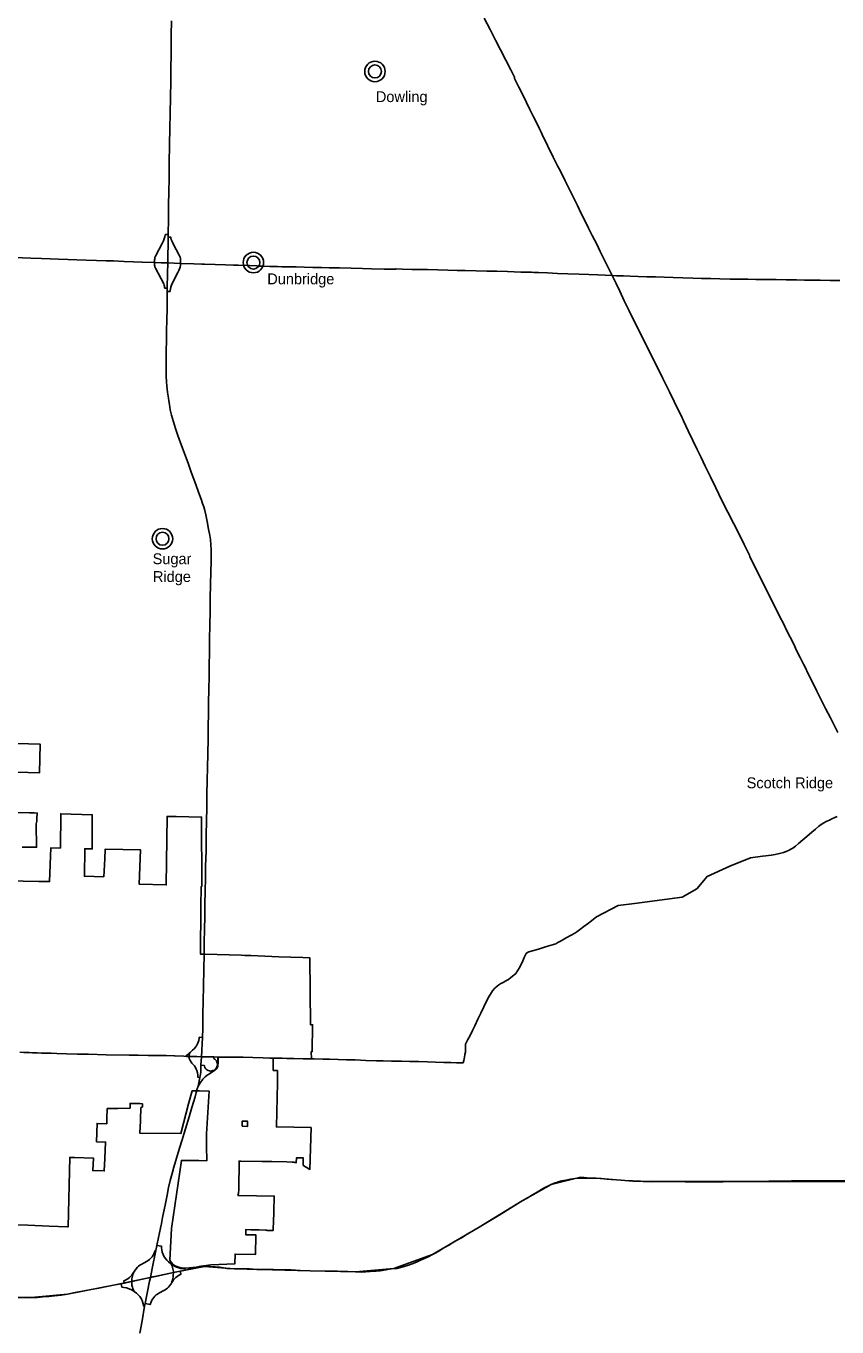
# Model space of a CAD drawing. Extents: x 0 to 851, y 0 to 440.
# Drawn here: x 318.5 to 370.6, y 193.8 to 277.3 of the extents above; entities that cross this region are included whole.
import ezdxf

# ---------------------------------------------------------------- set-up
doc = ezdxf.new("R2010")
doc.units = 0
for name, color, linetype in [('DV_X_Corp_Line', 7, 'Continuous'), ('GM_X_Interchange_Ramps', 7, 'Continuous'), ('GM_X_Interstate_Route', 7, 'Continuous'), ('GM_X_State_Route', 7, 'Continuous'), ('GM_X_US_Route', 7, 'Continuous'), ('RD_P_Fence', 7, 'Continuous')]:
    doc.layers.add(name, color=color, linetype=linetype)

msp = doc.modelspace()

# ---------------------------------------------------------------- linework, layer by layer
at = {"layer": 'DV_X_Corp_Line'}
for points in [[(317.154, 231.265), (319.399, 231.202), (319.371, 229.365), (317.197, 229.427)], [(317.314, 222.414), (319.328, 222.376), (320.015, 222.363), (320.095, 224.543), (320.714, 224.521), (320.728, 226.73), (322.756, 226.667), (322.751, 224.47), (322.278, 224.483), (322.256, 222.709), (323.491, 222.681), (323.555, 223.83), (323.583, 224.447), (325.855, 224.402), (325.773, 222.196), (327.504, 222.149), (327.565, 226.551), (328.151, 226.541), (329.777, 226.51), (329.803, 222.056), (329.756, 222.057), (329.733, 220.758), (329.716, 217.703), (329.816, 217.7), (330.002, 217.696), (332.325, 217.634), (332.55, 217.623), (332.612, 217.621), (332.951, 217.611), (334.75, 217.543), (336.273, 217.487), (336.736, 217.468), (336.778, 213.167), (336.911, 213.165), (336.892, 211.45), (336.827, 211.45), (336.838, 210.975), (335.612, 210.996), (334.383, 211.028), (334.378, 210.233), (334.652, 210.225), (334.655, 209.43), (334.589, 206.601), (336.813, 206.567), (336.735, 203.87), (336.488, 204.015), (336.297, 204.127), (336.308, 204.612), (335.868, 204.615), (335.859, 204.308), (335.772, 204.326), (335.709, 204.337), (335.605, 204.347), (335.262, 204.357), (334.283, 204.374), (333.64, 204.385), (332.31, 204.405), (332.189, 204.406), (332.166, 202.577), (332.141, 202.336), (332.111, 202.209), (332.165, 202.207), (334.443, 202.163), (334.418, 201.18), (334.39, 200.466), (334.382, 200.116), (334.368, 199.949), (334.07, 199.954), (333.997, 199.958), (333.94, 199.961), (333.878, 199.964), (333.488, 199.991), (332.939, 200.003), (332.616, 200.008), (332.611, 199.677), (333.273, 199.663), (333.241, 198.405), (331.928, 198.438), (331.91, 197.806), (330.381, 197.745), (330.066, 197.71), (329.74, 197.656), (329.423, 197.596), (328.998, 197.543), (328.695, 197.532), (328.471, 197.552), (328.325, 197.585), (328.126, 197.664), (327.939, 197.776), (327.737, 198.04), (327.836, 200.081), (328.478, 204.451), (328.884, 204.446), (329.593, 204.437), (330.11, 204.435), (330.092, 205.369), (330.102, 206.155), (330.263, 208.906), (329.645, 208.917), (329.609, 208.918), (329.417, 208.923), (329.364, 208.92), (329.17, 208.923), (328.929, 208.08), (328.451, 206.174), (325.819, 206.201), (325.849, 207), (325.853, 207.102), (325.877, 207.812), (325.902, 207.855), (325.935, 207.878), (325.973, 207.888), (325.978, 208.095), (325.814, 208.1), (325.186, 208.115), (325.184, 207.813), (324.397, 207.781), (323.714, 207.788), (323.709, 207.603), (323.702, 207.329), (323.695, 207.055), (323.691, 206.9), (323.689, 206.808), (323.067, 206.828), (323.036, 205.65), (323.614, 205.635), (323.57, 204.578), (323.529, 203.775), (322.786, 203.795), (322.828, 204.601), (321.607, 204.637), (321.314, 204.648), (321.207, 200.185), (321.162, 200.187), (319.986, 200.232), (318.618, 200.295), (316.035, 200.378)], [(317.713, 226.813), (318.72, 226.789), (319.019, 226.78), (319.219, 226.773), (319.205, 226.436), (319.197, 226.327), (319.187, 226.245), (319.16, 226.082), (319.179, 224.576), (318.247, 224.587)]]:
    msp.add_lwpolyline(points, dxfattribs=at)
msp.add_lwpolyline([(332.384, 206.65), (332.733, 206.638), (332.738, 206.967), (332.396, 206.98)], close=True, dxfattribs=at)
for centre, radius in [((340.916, 274.421), 0.658), ((340.916, 274.421), 0.417), ((333.108, 262.141), 0.658), ((333.108, 262.141), 0.417), ((327.268, 244.397), 0.658), ((327.268, 244.397), 0.417)]:
    msp.add_circle(centre, radius, dxfattribs=at)
at = {"layer": 'GM_X_Interchange_Ramps'}
for points in [[(329.036, 211.388), (329.054, 211.367), (329.007, 211.314), (328.985, 211.262), (328.977, 211.193), (328.975, 211.133)], [(330.816, 211.097), (330.816, 211.041), (330.808, 210.667), (330.791, 210.666)], [(327.965, 197.248), (327.967, 197.315), (327.954, 197.409), (327.94, 197.496), (327.92, 197.574), (327.888, 197.667), (327.849, 197.737), (327.867, 197.762)], [(325.295, 196.664), (325.289, 196.54), (325.307, 196.428), (325.336, 196.3), (325.355, 196.219), (325.383, 196.157), (325.416, 196.099), (325.436, 196.074), (325.421, 196.049)], [(325.409, 197.253), (325.428, 197.241), (325.366, 197.117), (325.333, 197.011), (325.314, 196.923), (325.3, 196.844), (325.299, 196.777), (325.295, 196.664)], [(327.871, 196.617), (327.856, 196.626), (327.904, 196.756), (327.937, 196.874), (327.953, 196.954), (327.96, 197.084), (327.965, 197.248)]]:
    msp.add_lwpolyline(points, dxfattribs=at)
at = {"layer": 'GM_X_Interstate_Route'}
for points in [[(327.534, 257.675), (327.534, 257.681), (327.535, 257.751), (327.544, 258.449), (327.562, 259.181), (327.571, 260.282), (327.576, 260.5), (327.595, 261.448), (327.604, 262.116), (327.626, 263.766), (327.628, 263.941), (327.649, 264.971), (327.66, 265.881), (327.672, 266.657), (327.687, 267.567), (327.702, 268.494), (327.725, 269.773), (327.742, 270.743), (327.756, 271.768), (327.772, 272.732), (327.795, 273.826), (327.797, 274.243), (327.798, 274.532), (327.817, 275.623), (327.831, 276.758), (327.849, 277.678)], [(329.939, 217.725), (329.953, 218.473), (329.966, 219.286), (329.982, 220.116), (329.995, 220.925), (330.014, 221.758), (330.028, 222.617), (330.039, 223.363), (330.065, 224.336), (330.082, 225.341), (330.094, 226.268), (330.108, 227.117), (330.124, 227.937), (330.143, 228.9), (330.155, 229.683), (330.17, 230.589), (330.192, 231.52), (330.205, 232.383), (330.22, 233.131), (330.229, 233.813), (330.248, 234.774), (330.259, 235.492), (330.267, 236.275), (330.28, 237.094), (330.296, 237.927), (330.312, 238.864), (330.325, 239.71), (330.339, 240.57), (330.35, 241.46), (330.372, 242.249), (330.392, 242.96), (330.393, 243.293), (330.386, 243.699), (330.369, 244.002), (330.354, 244.355), (330.303, 244.602), (330.226, 245.013), (330.133, 245.496), (330.046, 245.928), (329.979, 246.208), (329.917, 246.442), (329.839, 246.662), (329.751, 246.943), (329.587, 247.387), (329.408, 247.881), (329.241, 248.335), (329.096, 248.738), (328.907, 249.25), (328.736, 249.708), (328.595, 250.101), (328.428, 250.551), (328.248, 251.036), (328.094, 251.49), (327.977, 251.906), (327.853, 252.332), (327.767, 252.683), (327.708, 253.011), (327.671, 253.253), (327.644, 253.425), (327.589, 253.82), (327.538, 254.2), (327.515, 254.503), (327.502, 254.812), (327.498, 255.209), (327.506, 255.844), (327.51, 256.448), (327.527, 257.16), (327.534, 257.675)], [(329.868, 213.855), (329.891, 214.689), (329.907, 215.669), (329.921, 216.69), (329.939, 217.725)], [(329.763, 211.114), (329.829, 212.36), (329.853, 212.939), (329.866, 213.792), (329.868, 213.845), (329.868, 213.855)], [(329.551, 209.228), (329.551, 209.228), (329.579, 209.33), (329.668, 209.785), (329.682, 209.875), (329.722, 210.133), (329.736, 210.563), (329.763, 211.114)], [(329.435, 208.806), (329.435, 208.809), (329.502, 209.046), (329.551, 209.228)], [(328.122, 204.455), (328.276, 204.962), (328.511, 205.71), (328.743, 206.477), (328.978, 207.244), (329.16, 207.858), (329.356, 208.529), (329.435, 208.806)], [(327.173, 200.274), (327.276, 200.787), (327.431, 201.572), (327.566, 202.218), (327.664, 202.709), (327.765, 203.17), (327.883, 203.608), (327.999, 204.015), (328.101, 204.382), (328.122, 204.455)], [(326.487, 196.932), (326.605, 197.517), (326.849, 198.674), (326.914, 198.996), (327.012, 199.503), (327.138, 200.099), (327.167, 200.245), (327.173, 200.274)], [(325.813, 193.357), (325.958, 194.139), (326.115, 195.079), (326.15, 195.254), (326.438, 196.688), (326.487, 196.932)]]:
    msp.add_lwpolyline(points, dxfattribs=at)
at = {"layer": 'GM_X_State_Route'}
for points in [[(356.154, 261.303), (355.918, 261.775), (355.651, 262.344), (355.39, 262.857), (355.16, 263.326), (354.88, 263.877), (354.644, 264.352), (354.396, 264.842), (354.169, 265.295), (353.924, 265.811), (353.691, 266.271), (353.433, 266.803), (353.14, 267.388), (352.794, 268.091), (352.649, 268.363), (352.376, 268.914), (351.669, 270.364), (351.588, 270.528), (351.487, 270.738), (351.3, 271.132), (351.108, 271.505), (350.875, 271.978), (350.654, 272.423), (350.407, 272.923), (350.164, 273.413), (349.889, 273.977), (349.882, 274.028), (349.877, 274.058), (349.64, 274.52), (349.329, 275.136), (348.977, 275.82), (348.662, 276.425), (348.313, 277.112), (347.941, 277.85)], [(327.628, 263.941), (327.451, 263.943), (327.445, 263.915), (327.416, 263.786), (327.38, 263.671), (327.33, 263.541), (327.273, 263.412), (326.814, 262.552), (326.781, 262.463), (326.765, 262.389), (326.76, 262.306), (326.758, 262.223), (326.757, 262.137)], [(328.43, 262.089), (328.432, 262.162), (328.433, 262.284), (328.423, 262.382), (328.401, 262.479), (328.342, 262.611), (327.945, 263.334), (327.902, 263.442), (327.862, 263.54), (327.829, 263.63), (327.81, 263.739), (327.807, 263.763), (327.626, 263.766)], [(316.321, 262.509), (316.63, 262.498), (317.153, 262.476), (317.702, 262.46), (318.268, 262.444), (318.801, 262.422), (319.494, 262.4), (320.053, 262.381), (320.586, 262.365), (321.196, 262.341), (321.765, 262.322), (322.371, 262.302), (323.021, 262.281), (323.647, 262.26), (324.13, 262.246), (324.468, 262.233), (324.803, 262.218), (325.399, 262.187), (325.938, 262.159), (325.958, 262.158), (325.96, 262.158)], [(325.96, 262.158), (326.757, 262.137), (327.179, 262.13), (327.604, 262.116), (328.43, 262.089), (329.277, 262.063), (329.791, 262.046), (329.801, 262.045)], [(326.757, 262.137), (326.754, 262.025), (326.754, 261.982), (326.765, 261.919), (326.78, 261.86), (326.813, 261.775), (327.343, 260.782), (327.374, 260.698), (327.388, 260.623), (327.406, 260.533), (327.41, 260.504), (327.576, 260.5)], [(327.571, 260.282), (327.746, 260.278), (327.751, 260.322), (327.781, 260.48), (327.815, 260.617), (327.869, 260.749), (328.252, 261.511), (328.322, 261.634), (328.362, 261.731), (328.402, 261.839), (328.42, 261.949), (328.428, 262.021), (328.43, 262.089)], [(329.801, 262.045), (329.971, 262.04), (330.661, 262.016), (331.305, 261.998), (331.821, 261.982), (332.139, 261.971)], [(332.139, 261.971), (332.139, 261.971), (332.867, 261.947), (333.333, 261.922), (333.383, 261.911), (333.597, 261.906)], [(333.597, 261.906), (333.738, 261.903), (334.171, 261.892), (334.536, 261.887), (334.57, 261.886), (334.648, 261.884), (334.939, 261.877), (335.438, 261.865), (335.851, 261.862), (336.367, 261.847), (336.927, 261.83), (336.976, 261.829)], [(336.976, 261.829), (337.477, 261.823), (337.976, 261.808), (338.64, 261.796), (339.398, 261.778), (340.106, 261.761), (340.702, 261.746), (341.51, 261.727), (342.151, 261.712), (342.233, 261.725), (342.289, 261.735), (342.678, 261.726), (343.288, 261.705), (343.791, 261.696), (344.3, 261.687), (344.961, 261.668), (345.605, 261.649), (346.198, 261.635), (346.711, 261.623), (347.429, 261.609), (348.109, 261.593), (348.746, 261.578), (349.44, 261.561), (350.298, 261.534), (350.965, 261.515), (351.113, 261.51), (351.431, 261.5), (352.001, 261.473), (352.648, 261.444), (353.301, 261.418), (354.032, 261.391), (354.652, 261.366), (355.235, 261.345), (355.715, 261.324), (356.154, 261.303)], [(370.65, 231.945), (370.413, 232.408), (370.176, 232.89), (369.862, 233.499), (369.564, 234.082), (369.305, 234.608), (369.052, 235.128), (368.773, 235.682), (368.53, 236.178), (368.445, 236.347), (368.238, 236.756), (368.005, 237.226), (367.826, 237.62), (367.589, 238.075), (367.38, 238.48), (367.131, 238.99), (366.955, 239.344), (365.01, 243.264), (364.973, 243.338), (364.627, 244.032), (364.307, 244.681), (363.964, 245.358), (363.589, 246.113), (363.211, 246.857), (362.815, 247.673), (362.476, 248.38), (362.14, 249.066), (361.878, 249.61), (361.622, 250.134), (361.347, 250.698), (361.04, 251.33), (360.735, 251.981), (360.581, 252.311), (360.445, 252.584), (359.829, 253.835), (359.401, 254.697), (359.06, 255.392), (358.275, 256.96), (357.886, 257.749), (357.569, 258.384), (357.255, 259.044), (356.923, 259.686), (356.644, 260.3), (356.405, 260.789), (356.154, 261.303)], [(356.154, 261.303), (356.432, 261.296), (356.881, 261.282), (357.303, 261.269), (357.833, 261.249), (358.379, 261.233), (358.936, 261.216), (359.489, 261.2), (360.072, 261.179), (360.696, 261.16), (361.329, 261.142), (361.899, 261.122), (362.499, 261.107), (363.079, 261.093), (363.726, 261.078), (364.37, 261.072), (364.877, 261.067), (365.393, 261.061), (365.967, 261.058), (366.701, 261.043), (367.332, 261.035), (368.002, 261.022), (368.522, 261.013), (368.995, 261.009), (369.515, 261), (370.155, 260.998), (370.789, 260.993)], [(365.812, 223.991), (366.028, 224.016), (366.371, 224.062), (366.624, 224.106), (366.914, 224.176), (367.154, 224.241), (367.33, 224.308), (367.529, 224.39), (367.631, 224.452), (367.757, 224.526), (367.931, 224.653), (368.116, 224.813), (368.4, 225.051), (368.661, 225.267), (368.986, 225.538), (369.218, 225.737), (369.434, 225.924), (369.588, 226.031), (369.758, 226.138), (369.908, 226.225), (370.111, 226.321), (370.274, 226.394), (370.464, 226.48), (370.613, 226.557)], [(355.151, 220.109), (356.532, 220.828), (357.597, 220.961), (360.657, 221.36), (361.588, 221.893), (362.253, 222.692), (363.717, 223.357), (365.047, 223.89), (365.812, 223.991)], [(350.69, 217.798), (350.716, 217.816), (350.794, 217.848), (351.047, 217.926), (351.419, 218.034), (351.8, 218.149), (352.081, 218.233), (352.392, 218.33), (352.527, 218.377), (352.656, 218.451), (352.87, 218.57), (353.21, 218.76), (353.519, 218.931), (353.764, 219.06), (353.88, 219.137), (354.047, 219.261), (354.344, 219.476), (354.634, 219.697), (354.75, 219.786), (354.826, 219.844), (355.065, 220.04), (355.151, 220.109)], [(346.591, 210.724), (346.634, 210.867), (346.669, 211.082), (346.701, 211.256), (346.733, 211.407), (346.743, 211.535), (346.74, 211.703), (346.733, 211.834), (346.739, 211.928), (346.784, 212.007), (346.884, 212.23), (347.024, 212.482), (347.176, 212.804), (347.324, 213.107), (347.528, 213.525), (347.715, 213.907), (347.902, 214.319), (348.079, 214.684), (348.254, 214.996), (348.341, 215.145), (348.477, 215.34), (348.618, 215.515), (348.766, 215.659), (348.872, 215.74), (349.001, 215.814), (349.144, 215.878), (349.324, 215.985), (349.487, 216.082), (349.648, 216.199), (349.836, 216.352), (349.959, 216.47), (350.084, 216.625), (350.185, 216.801), (350.315, 217.039), (350.418, 217.279), (350.506, 217.482), (350.612, 217.708), (350.631, 217.738), (350.651, 217.77), (350.69, 217.798), (350.69, 217.798)], [(329.829, 212.36), (329.634, 212.368), (329.621, 212.298), (329.594, 212.166), (329.558, 212.043), (329.515, 211.936), (329.455, 211.822), (329.384, 211.724), (329.305, 211.631), (329.204, 211.532), (329.036, 211.388), (328.98, 211.339), (328.893, 211.264), (328.826, 211.223), (328.817, 211.218), (328.816, 211.136)], [(322.429, 211.271), (322.305, 211.274), (321.808, 211.274), (321.099, 211.309), (320.477, 211.328), (320.12, 211.334), (319.865, 211.341), (319.488, 211.353), (319.218, 211.363), (318.914, 211.373), (318.697, 211.383), (318.359, 211.397), (318.102, 211.412)], [(328.053, 211.176), (328.025, 211.177), (327.5, 211.188), (327.091, 211.199), (326.357, 211.199), (325.712, 211.21), (325.13, 211.219), (323.646, 211.237), (322.516, 211.269), (322.429, 211.271)], [(328.646, 211.145), (328.053, 211.176)], [(330.033, 211.11), (330.02, 211.11), (330.012, 211.11), (329.763, 211.114), (329.464, 211.119), (328.975, 211.133), (328.816, 211.136), (328.646, 211.145)], [(328.975, 211.133), (328.974, 211.085), (328.99, 210.994), (329.022, 210.916), (329.06, 210.843), (329.114, 210.773), (329.163, 210.712), (329.243, 210.622), (329.324, 210.522), (329.393, 210.413), (329.437, 210.322), (329.472, 210.233), (329.514, 210.081), (329.531, 209.951), (329.535, 209.829), (329.533, 209.806), (329.668, 209.785)], [(329.551, 209.228), (329.7, 209.465), (329.869, 209.676), (330.013, 209.824), (330.14, 209.922), (330.277, 210.026), (330.427, 210.124), (330.553, 210.189), (330.632, 210.241), (330.727, 210.329), (330.8, 210.438), (330.826, 210.51), (330.844, 210.764), (330.852, 211.096)], [(330.573, 211.102), (330.571, 211.002), (330.621, 210.969), (330.689, 210.904), (330.732, 210.852), (330.766, 210.791), (330.787, 210.728), (330.791, 210.666), (330.792, 210.642), (330.791, 210.57), (330.761, 210.47), (330.719, 210.389), (330.659, 210.314), (330.584, 210.255), (330.512, 210.222), (330.428, 210.203), (330.361, 210.198), (330.283, 210.208), (330.192, 210.235), (330.121, 210.274), (330.057, 210.327), (329.991, 210.421), (329.956, 210.498), (329.944, 210.557), (329.736, 210.563)], [(330.852, 211.096), (330.816, 211.097), (330.573, 211.102), (330.033, 211.11)], [(330.852, 211.096), (331.04, 211.095), (331.093, 211.095)], [(331.093, 211.095), (331.372, 211.094), (331.709, 211.088), (331.736, 211.088)], [(331.736, 211.088), (331.953, 211.084), (332.376, 211.081), (332.378, 211.081)], [(332.378, 211.081), (332.458, 211.08), (333.065, 211.07), (333.74, 211.038), (334.171, 211.033)], [(334.171, 211.033), (334.348, 211.031), (334.619, 211.025), (334.621, 211.025)], [(334.621, 211.025), (334.962, 211.018), (335.252, 211.01)], [(335.252, 211.01), (335.597, 211), (335.703, 210.998)], [(335.703, 210.998), (336.312, 210.985), (336.875, 210.978)], [(336.875, 210.978), (336.875, 210.978), (337.021, 210.976), (337.568, 210.967), (337.995, 210.958), (338.559, 210.938), (339.089, 210.923), (339.64, 210.908), (340.321, 210.883), (341.013, 210.857), (341.381, 210.855), (341.44, 210.855), (341.98, 210.839), (342.632, 210.828), (343.152, 210.817), (343.706, 210.801), (344.287, 210.785), (344.814, 210.77), (345.331, 210.752), (345.798, 210.738), (346.161, 210.73), (346.591, 210.724)], [(328.716, 197.404), (328.697, 197.497), (328.593, 197.501), (328.454, 197.518), (328.318, 197.547), (328.174, 197.589), (328.044, 197.649), (327.915, 197.727), (327.867, 197.762), (327.8, 197.81), (327.661, 197.927), (327.543, 198.046), (327.434, 198.179), (327.355, 198.307), (327.304, 198.41), (327.251, 198.558), (327.218, 198.699), (327.204, 198.838), (327.206, 198.94), (326.914, 198.996)], [(326.849, 198.674), (326.8, 198.684), (326.791, 198.653), (326.751, 198.549), (326.709, 198.448), (326.658, 198.365), (326.595, 198.267), (326.51, 198.17), (326.429, 198.09), (326.352, 198.032), (326.247, 197.96), (326.14, 197.9), (325.898, 197.767), (325.807, 197.713), (325.73, 197.659), (325.652, 197.586), (325.576, 197.493), (325.47, 197.346), (325.409, 197.253), (325.366, 197.188), (325.294, 197.086), (325.218, 196.997), (325.138, 196.922), (325.047, 196.855), (324.96, 196.801), (324.851, 196.743), (324.777, 196.709), (324.807, 196.561)], [(326.15, 195.254), (326.468, 195.191), (326.469, 195.195), (326.534, 195.359), (326.586, 195.47), (326.644, 195.564), (326.708, 195.65), (326.786, 195.732), (326.87, 195.807), (326.946, 195.859), (327.04, 195.92), (327.117, 195.961), (327.321, 196.067), (327.437, 196.137), (327.515, 196.192), (327.593, 196.251), (327.661, 196.319), (327.728, 196.394), (327.817, 196.528), (327.871, 196.617), (327.906, 196.676), (327.975, 196.776), (328.058, 196.867), (328.133, 196.937), (328.215, 197.005), (328.3, 197.062), (328.387, 197.112), (328.451, 197.143), (328.411, 197.342)], [(324.613, 196.523), (324.652, 196.311), (324.789, 196.289), (324.95, 196.256), (325.12, 196.204), (325.287, 196.132), (325.421, 196.049), (325.449, 196.032), (325.59, 195.927), (325.693, 195.828), (325.806, 195.709), (325.899, 195.571), (325.962, 195.444), (326.009, 195.306), (326.045, 195.179), (326.058, 195.091), (326.115, 195.079)]]:
    msp.add_lwpolyline(points, dxfattribs=at)
at = {"layer": 'GM_X_US_Route'}
for points in [[(352.591, 203.041), (352.594, 203.042), (352.695, 203.076), (352.929, 203.137), (353.186, 203.188), (353.47, 203.241), (353.784, 203.3), (353.976, 203.343), (354.054, 203.361), (354.347, 203.346), (354.723, 203.323)], [(354.723, 203.323), (355.119, 203.306), (355.461, 203.284), (355.804, 203.258), (356.092, 203.234), (356.434, 203.205), (356.729, 203.177), (356.974, 203.158), (357.226, 203.145), (357.488, 203.128), (357.794, 203.12), (358.157, 203.104), (358.476, 203.099), (358.708, 203.086), (358.87, 203.092), (358.973, 203.096), (359.343, 203.097), (359.791, 203.099), (360.265, 203.1), (360.628, 203.101), (360.722, 203.095), (360.839, 203.085), (360.991, 203.081), (361.387, 203.085), (361.75, 203.082), (362.141, 203.086), (362.554, 203.085), (363.102, 203.084), (363.29, 203.085), (367.677, 203.144), (371.958, 203.137)], [(332.863, 197.477), (333.327, 197.454), (333.845, 197.44), (334.39, 197.435), (335.012, 197.413), (335.502, 197.413), (336.114, 197.385), (336.758, 197.369), (338.506, 197.342), (339.174, 197.311), (339.671, 197.295), (340.024, 197.283), (340.323, 197.294), (340.61, 197.306), (340.999, 197.336), (341.242, 197.365), (341.624, 197.415), (341.834, 197.455), (342.121, 197.516), (342.316, 197.503), (342.56, 197.564), (342.797, 197.629), (343.079, 197.722), (343.309, 197.807), (343.581, 197.921), (343.85, 198.045), (344.146, 198.179), (344.384, 198.283), (344.613, 198.402), (344.827, 198.517), (345.08, 198.665), (345.343, 198.827), (345.671, 199.017), (346.07, 199.255), (346.47, 199.483), (346.845, 199.709), (347.248, 199.95), (347.617, 200.166), (347.935, 200.366), (348.369, 200.621), (348.779, 200.872), (349.168, 201.107), (349.581, 201.362), (349.865, 201.533), (350.104, 201.681), (350.381, 201.846), (350.691, 202.029), (351.029, 202.232), (351.327, 202.409), (351.617, 202.583), (351.835, 202.705), (352.029, 202.801), (352.244, 202.906), (352.492, 203.008), (352.591, 203.041)], [(326.661, 196.969), (326.704, 196.978), (327.965, 197.248), (328.411, 197.342), (328.716, 197.404), (329.311, 197.523), (329.574, 197.58), (329.723, 197.606), (329.959, 197.627), (330.233, 197.638), (330.275, 197.639), (330.302, 197.638)], [(330.302, 197.638), (330.653, 197.625), (330.948, 197.592), (331.189, 197.552)], [(331.189, 197.552), (331.394, 197.517), (331.901, 197.495), (332.248, 197.493), (332.338, 197.491)], [(332.338, 197.491), (332.774, 197.482), (332.863, 197.477)], [(318.457, 195.635), (318.84, 195.642), (319.229, 195.653), (319.579, 195.681), (319.955, 195.708), (320.321, 195.743), (320.764, 195.796), (321.175, 195.867), (321.663, 195.956), (322.134, 196.046), (322.692, 196.158), (323.18, 196.247), (323.692, 196.35), (324.217, 196.452), (324.613, 196.523), (324.807, 196.561), (325.295, 196.664), (326.17, 196.864), (326.487, 196.932)], [(326.487, 196.932), (326.654, 196.967), (326.661, 196.969)]]:
    msp.add_lwpolyline(points, dxfattribs=at)
at = {"layer": 'RD_P_Fence'}
msp.add_lwpolyline([(317.186, 195.649), (318.84, 195.642), (321.175, 195.867), (324.217, 196.452), (326.17, 196.864), (327.965, 197.248), (329.959, 197.627), (331.901, 197.495), (336.758, 197.369), (339.671, 197.295), (342.121, 197.516), (344.613, 198.402), (347.617, 200.166), (350.381, 201.846), (352.244, 202.906), (353.784, 203.3), (355.119, 203.306), (356.974, 203.158), (358.476, 203.099), (368.358, 203.099), (376.986, 203.089)], dxfattribs=at)

# ---------------------------------------------------------------- texts
at = {"layer": 'DV_X_Corp_Line'}
for s, height, p in [('Dowling', 0.6979, (340.975, 272.451)), ('Dunbridge', 0.6979, (334, 260.744)), ('Sugar', 0.6979, (326.634, 242.762)), ('Ridge', 0.6979, (326.654, 241.616)), ('Scotch Ridge', 0.69792, (364.796, 228.366))]:
    msp.add_text(s, height=height, rotation=0.00001, dxfattribs=at).set_placement(p)

doc.saveas('drawing.dxf')
